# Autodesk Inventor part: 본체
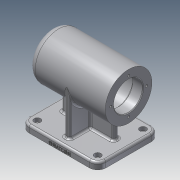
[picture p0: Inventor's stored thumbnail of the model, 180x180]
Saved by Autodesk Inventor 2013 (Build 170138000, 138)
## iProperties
Created: 2020-10
Part Number: 본체
Material: 알루미늄 6061
Document SubType Name: Modeling
Designer: user
Density: 2.71 g/cm^3
Mass: 1030.08 g
Surface Area: 757.984 cm^2
Volume: 380.102 cm^3
Author: user
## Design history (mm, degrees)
sketch "스케치1"
  geometry: C1 r 34 at (0, 0); 1 further point
  constraints: 1 centre point, 1 coincident
  dimensions: "d0" = 68 diameter of C1
extrude "돌출1" new body sketch "스케치1" stored distance "d1" = 112; taper "d2" = 0 deg
sketch "스케치2"
  geometry: L1 (34, -56)-(-34, -56) reference; L2 (-34, -56)-(-34, 56) reference; L3 (-34, 56)-(34, 56) reference; L4 (34, 56)-(34, -56) reference; L5 (0, -56)-(21, -56); L6 (21, -56)-(21, -41); L7 (21, -41)-(24, -41); L8 (24, -41)-(24, 13); L9 (24, 13)-(21, 13); L10 (21, 13)-(21, 25); L11 (21, 25)-(17.5, 25); L12 (17.5, 25)-(17.5, 43); L13 (17.5, 43)-(16, 43); L14 (16, 43)-(16, 47); L15 (16, 47)-(10.5, 47); L16 (10.5, 47)-(10.5, 50); L17 (10.5, 50)-(0, 50); L18 (0, 50)-(0, -56); 1 further point
  constraints: 28 end point, 7 parallel, 5 perpendicular, 1 collinear, 1 midpoint, 1 point on line
  dimensions: "d3" = 3 distance of L15.end L16.end; "d5" = 4 distance of L13.end L14.end; "d6" = 18 distance of L11.end L12.end; "d7" = 12 distance of L9.end L10.end; "d8" = 54 distance of L7.end L8.end; "d9" = 15 distance of L5.end L6.end; "d10" = 42 diameter of L6 L18; "d11" = 48 diameter of L8 L18; "d12" = 42 diameter of L10 L18; "d13" = 21 diameter of L16 L18; "d14" = 32 diameter of L14 L18; "d15" = 35 diameter of L12 L18
revolve "회전1" sketch "스케치2" stored, may be unused: angle "d16" = 90 deg
sketch "스케치3" dims "d17" = 52
  geometry: C1 r 21 at (0, 0) reference; C2 r 34 at (0, 0) reference; 2 further points
  constraints: 2 vertical alignment, 1 coincident, 2 other
hole "구멍1" sketch "스케치3" at (0, 26) diameter "d18" = 3.242; stored, may be unused: countersink angle "d22" = 90 deg, drill point angle "d24" = 118 deg; dims "d19" = 8, "d20" = 4, "d21" = 2, "d23" = 11
node "작업 평면1"
sketch "스케치4"
  geometry: L1 (34, -56)-(34, 56) reference; L2 (34, 56)-(-34, 56) reference; L3 (-34, -56)-(34, -56) reference; L4 (-34, -56)-(-34, 56) reference; L5 (-45, 56)-(45, 56); L6 (45, 56)-(45, -56); L7 (45, -56)-(-45, -56); L8 (-45, -56)-(-45, 56); L9 (-45, 56)-(45, -56); L10 (45, 56)-(-45, -56); 1 further point
  constraints: 12 end point, 2 midpoint, 2 parallel, 1 horizontal, 1 perpendicular
  dimensions: "d29" = 90 distance of L6.end L7.end; "d30" = 112 distance of L5.end L6.end
extrude "돌출2" join sketch "스케치4" distance "d31" = 10; taper "d32" = 0 deg
sketch "스케치5"
  geometry: L1 (56, -45)-(56, 45) reference; L2 (-56, 45)-(-56, -45) reference; L3 (-38, -4)-(38, -4); L4 (38, -4)-(38, 4); L5 (38, 4)-(-38, 4); L6 (-38, 4)-(-38, -4); 2 further points
  constraints: 8 end point, 2 parallel, 1 horizontal, 1 horizontal alignment, 1 midpoint, 1 perpendicular
  dimensions: "d33" = 8 distance of L3.end L4.end; "d35" = 18 distance between parallel lines of L6 L2; "d36" = 18 distance between parallel lines of L1 L4
extrude "돌출3" join sketch "스케치5" stored distance "d37" = 10; taper "d38" = 0 deg
sketch "스케치6"
  geometry: L1 (64, 45)-(74, 45) reference; L2 (74, 45)-(74, -45) reference; L3 (74, -45)-(64, -45) reference; L4 (64, -45)-(64, -4) reference; L5 (64, -4)-(33.764, -4) reference; L6 (33.764, 4)-(64, 4) reference; L7 (64, 4)-(64, 45) reference; L8 (0, -34)-(64, -34); C1 r 24 at (0, 0) reference; A1 r 34 centre (0, 0) between (33.764, 4) and (33.764, -4) reference; 1 further point
  constraints: 2 end point, 1 perpendicular, 1 point on circle, 1 point on line, 1 tangent
feature "리브1" sketch "스케치6" dims "d39" = 1, "d40" = 8, "d41" = 0, "d42" = 0, "d43" = 1, "d44" = 1
fillet "모깎기1" dims "d45" = 12
sketch "스케치7"
  geometry: A1 r 12 centre (44, -33) between (44, -45) and (56, -33) reference; A2 r 12 centre (44, 33) between (56, 33) and (44, 45) reference; A3 r 12 centre (-44, 33) between (-44, 45) and (-56, 33) reference; A4 r 12 centre (-44, -33) between (-56, -33) and (-44, -45) reference; 5 further points
  constraints: 4 coincident
hole "구멍2" sketch "스케치7" at (-44, 33), (44, 33), (44, -33), (-44, -33) diameter "d46" = 5.5; stored, may be unused: countersink angle "d50" = 90 deg, drill point angle "d52" = 118 deg; dims "d47" = 5.5, "d48" = 9.5, "d49" = 5.4, "d51" = 11
fillet "모깎기2" dims "d53" = 10
sketch "스케치8"
  geometry: L1 (0, 100)-(-10, 100) reference; 3 further points
  constraints: 1 other
  dimensions: "d54" = 3 horizontal distance of point (0, 88) point (-3, 45); "d55" = 55 distance from line of L1 point (-3, 45)
feature "엠보싱1" sketch "스케치8" dims "d56" = 0.5, "d57" = 0
fillet "모깎기3" dims "d58" = 3
fillet "모깎기4" dims "d59" = 0.3
fillet "모깎기5" dims "d60" = 3
chamfer "모따기1" distance "d61" = 1; stored, may be unused: second distance "d62" = 2, angle "d63" = 45 deg
fillet "모깎기6" dims "d64" = 3
fillet "모깎기7" dims "d65" = 3
fillet "모깎기8" dims "d66" = 3
fillet "모깎기9" dims "d67" = 3
fillet "모깎기10" dims "d68" = 3
node "솔리드1"
pattern_circular "원형 패턴1" dims angle "d26" = 360 deg
mirror "대칭1"
node "절단 모서리 투영1"
node "절단 모서리 투영2"
other parameters: "d28" = 74
